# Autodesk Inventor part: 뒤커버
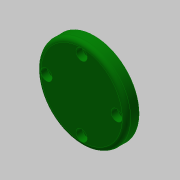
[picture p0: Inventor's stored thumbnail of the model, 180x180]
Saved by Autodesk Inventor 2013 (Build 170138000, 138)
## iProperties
Created: 2019-01
Part Number: 뒤커버
Material: 일반
Document SubType Name: Modeling
Designer: mduedu
Density: 1 g/cm^3
Author: mduedu
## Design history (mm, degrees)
sketch "스케치1"
  geometry: L1 (0, 0)-(9, 0); L2 (9, 0)-(9, 32); L3 (9, 32)-(0, 32); L4 (0, 32)-(0, 0); L5 (9, 0)-(12, 0); L6 (12, 0)-(12, 20); L7 (12, 20)-(9, 20); L8 (9, 20)-(9, 0)
  constraints: 16 end point, 4 parallel, 2 horizontal, 2 perpendicular
  dimensions: "d0" = 12 distance between parallel lines of L6 L4; "d2" = 64 diameter of L3 L1; "d3" = 40 diameter of L7 L5; "d4" = 3 distance between parallel lines of L6 L2
revolve "회전1" sketch "스케치1" stored, may be unused: angle "d5" = 90 deg
sketch "스케치4"
  geometry: C1 r 15 at (0, 0); 1 further point
  constraints: 1 centre point, 1 coincident
  dimensions: "d24" = 30 diameter of C1
extrude "돌출1" cut sketch "스케치4" distance "d25" = 6; taper "d26" = 0 deg
fillet "모깎기4" dims "d27" = 3
fillet "모깎기3" dims "d18" = 3
chamfer "모따기2" distance "d28" = 1; stored, may be unused: second distance "d29" = 2, angle "d30" = 45 deg
sketch "스케치3" dims "d19" = 50
  geometry: 6 further points
  constraints: 2 vertical alignment, 1 coincident, 7 other
  dimensions: "d22" = 360 deg dimension on point (0, 0) point (0, 25) (derived)
sketch "스케치5"
  geometry: 4 further points
  constraints: 4 other
hole "구멍1" sketch "스케치5" at (-25, 0), (0, -25), (25, 0), (0, 25) diameter "d31" = 4.5; stored, may be unused: countersink angle "d35" = 90 deg, drill point angle "d37" = 0 deg; dims "d32" = 6, "d33" = 8, "d34" = 4.6, "d36" = 8
node "솔리드1"
